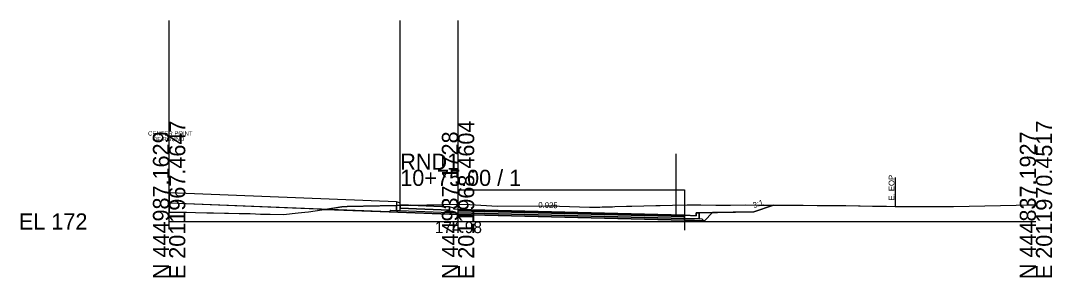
# Model space of a CAD drawing. Extents: x -26 to 153, y -10 to 6017.
# Drawn here: x -25.7 to 152.8, y 1490.3 to 1534.8 of the extents above; entities that cross this region are included whole.
import ezdxf

# ---------------------------------------------------------------- set-up
doc = ezdxf.new("R2010")
doc.units = 0
for name, color, linetype in [('Exist Cross Section Cell', 7, 'Continuous'), ('Exist XS Ground Line', 7, 'Continuous'), ('Prop CMT Conc Surface', 7, 'Continuous'), ('Prop CMT Concrete Structures', 7, 'Continuous'), ('Prop CMT Pvmt Course 1', 7, 'Continuous'), ('Prop CMT Pvmt Course 1 CG', 7, 'Continuous'), ('Prop CMT Pvmt Course 2', 7, 'Continuous'), ('Prop CMT Pvmt Course 3', 7, 'Continuous'), ('Prop CMT Pvmt Surface', 7, 'Continuous'), ('Prop CMT Shear Line', 7, 'Continuous'), ('Prop CMT Shear Line Text', 7, 'Continuous'), ('Prop CMT Slope Grass', 7, 'Continuous'), ('Prop CMT Subgrade Earthwork', 7, 'Continuous'), ('Prop XS Earthwork Shape', 7, 'Continuous'), ('Prop XS Label Text', 7, 'Continuous'), ('Prop XS SE Text', 7, 'Continuous'), ('Prop XS Side Slope Text', 7, 'Continuous'), ('Scratch_Level_1', 7, 'Continuous')]:
    doc.layers.add(name, color=color, linetype=linetype)

msp = doc.modelspace()

# ---------------------------------------------------------------- linework, layer by layer
at = {"layer": 'Exist Cross Section Cell'}
for p, q in [((50, 1500), (50, 1508.96)), ((0, 1500), (50, 1500)), ((50, 1500), (150, 1500))]:
    msp.add_line(p, q, dxfattribs=at)
at = {"layer": 'Exist XS Ground Line'}
msp.add_lwpolyline([(0, 1501.62), (1.6, 1501.62), (2.07, 1501.61), (2.68, 1501.61), (3, 1501.6), (4.59, 1501.54), (6.52, 1501.52), (7.09, 1501.51), (7.68, 1501.5), (9.59, 1501.43), (10.25, 1501.42), (12.1, 1501.38), (13.02, 1501.37), (14.04, 1501.36), (14.93, 1501.32), (15.79, 1501.29), (17.49, 1501.26), (19.81, 1501.21), (22.34, 1501.48), (23.51, 1501.6), (24.1, 1501.69), (26.41, 1501.99), (29.91, 1502.55), (30.8, 1502.57), (50.29, 1502.99), (52.03, 1502.93), (56.85, 1502.65), (65.22, 1502.7), (66.92, 1502.69), (67.55, 1502.67), (72.72, 1502.47), (73.83, 1502.48), (74.14, 1502.47), (74.54, 1502.5), (74.96, 1502.51), (76.73, 1502.55), (77.14, 1502.57), (79.15, 1502.64), (79.62, 1502.65), (80.08, 1502.66), (82.13, 1502.72), (84.25, 1502.75), (84.63, 1502.76), (84.99, 1502.77), (87.13, 1502.82), (89.64, 1502.87), (91.02, 1502.86), (91.56, 1502.87), (92, 1502.87), (94.63, 1502.85), (97.14, 1502.85), (99.69, 1502.86), (102.11, 1502.84), (103.21, 1502.83), (104.68, 1502.81), (107.1, 1502.82), (108.3, 1502.83), (108.73, 1502.83), (109.73, 1502.81), (112.12, 1502.79), (114.62, 1502.77), (117.12, 1502.74), (119.29, 1502.71), (119.61, 1502.7), (121.74, 1502.67), (122.11, 1502.66), (122.95, 1502.65), (124.12, 1502.63), (125.61, 1502.6), (129.55, 1502.61), (135.76, 1502.62), (146.58, 1502.85), (148.46, 1502.91), (150, 1502.9)], dxfattribs=at)
at = {"layer": 'Prop CMT Conc Surface'}
for points in [[(40, 1503.06), (39.96, 1503.17), (39.85, 1503.21), (39.34, 1503.4)], [(40, 1502.9), (40, 1503.06)], [(50, 1502.1), (49.25, 1502.12), (49.25, 1502.29), (48.5, 1502.54)], [(91.2, 1500.99), (91.2, 1501.49), (91.7, 1501.49)], [(89.21, 1501.12), (91.2, 1500.99)]]:
    msp.add_lwpolyline(points, dxfattribs=at)
at = {"layer": 'Prop CMT Concrete Structures'}
for points in [[(40, 1503.06), (39.96, 1503.17), (39.85, 1503.21), (39.34, 1503.4)], [(39.34, 1503.4), (39.34, 1501.9)], [(39.34, 1501.9), (40, 1501.9)], [(40, 1502.9), (40, 1503.06)], [(40, 1501.9), (40, 1502.9)], [(40, 1502.9), (40, 1502.31)], [(48.5, 1502.54), (40, 1502.88)], [(40, 1502.29), (48.5, 1501.95)], [(50, 1502.1), (49.25, 1502.12), (49.25, 1502.29), (48.5, 1502.54)], [(48.5, 1502.54), (48.5, 1501.55)], [(48.5, 1501.95), (48.5, 1502.54)], [(48.5, 1501.55), (50, 1501.52)], [(50, 1501.52), (50, 1502.1)], [(89.21, 1501.12), (91.2, 1500.99), (91.2, 1501.49), (91.7, 1501.49)], [(91.7, 1501.49), (91.7, 1500.47), (89.21, 1500.53)], [(89.21, 1500.53), (89.21, 1501.12)]]:
    msp.add_lwpolyline(points, dxfattribs=at)
at = {"layer": 'Prop CMT Pvmt Course 1'}
for points in [[(50, 1502.1), (89.21, 1501.12)], [(50, 1501.85), (50, 1502.1)], [(89.21, 1500.87), (50, 1501.85)], [(89.21, 1501.12), (89.21, 1500.87)]]:
    msp.add_lwpolyline(points, dxfattribs=at)
msp.add_lwpolyline([(50, 1501.85), (50, 1501.97), (50, 1501.97), (50, 1501.85)], close=True, dxfattribs=at)
at = {"layer": 'Prop CMT Pvmt Course 1 CG'}
for points in [[(50, 1501.18), (50, 1501.52)], [(89.21, 1500.53), (92.19, 1500.46), (92.53, 1500.12)], [(89.21, 1500.2), (89.21, 1500.53)], [(92.62, 1500.11), (89.21, 1500.2)]]:
    msp.add_lwpolyline(points, dxfattribs=at)
at = {"layer": 'Prop CMT Pvmt Course 2'}
for points in [[(50, 1501.52), (50, 1501.85)], [(50, 1501.85), (89.21, 1500.87)], [(89.21, 1500.53), (50, 1501.52)], [(89.21, 1500.87), (89.21, 1500.53)]]:
    msp.add_lwpolyline(points, dxfattribs=at)
at = {"layer": 'Prop CMT Pvmt Course 3'}
for points in [[(40, 1501.9), (48.5, 1501.55)], [(50, 1501.52), (89.21, 1500.53)], [(50, 1501.18), (50, 1501.52)], [(89.21, 1500.2), (50, 1501.18)], [(89.21, 1500.53), (89.21, 1500.2)]]:
    msp.add_lwpolyline(points, dxfattribs=at)
at = {"layer": 'Prop CMT Pvmt Surface'}
msp.add_lwpolyline([(50, 1502.1), (89.21, 1501.12)], dxfattribs=at)
at = {"layer": 'Prop CMT Shear Line'}
msp.add_line((0, 1498.64), (0, 1513.64), dxfattribs=at)
at = {"layer": 'Prop CMT Slope Grass'}
for p, q in [((39.34, 1503.38), (0, 1504.95)), ((38.06, 1501.66), (0, 1503.18))]:
    msp.add_line(p, q, dxfattribs=at)
msp.add_lwpolyline([(91.7, 1501.49), (101.16, 1501.68), (104.58, 1502.82)], dxfattribs=at)
at = {"layer": 'Prop CMT Subgrade Earthwork'}
for p, q in [((0, 1504.95), (0, 1501.62)), ((38.34, 1501.94), (38.06, 1501.66))]:
    msp.add_line(p, q, dxfattribs=at)
for points in [[(38.06, 1501.66), (50, 1501.18)], [(38.34, 1501.94), (39.34, 1501.9)], [(89.21, 1500.2), (92.62, 1500.11), (94.03, 1501.53)], [(50, 1501.18), (89.21, 1500.2)]]:
    msp.add_lwpolyline(points, dxfattribs=at)
at = {"layer": 'Prop XS Earthwork Shape'}
for points in [[(27.09, 1502.1), (0, 1503.18), (0, 1501.62), (1.6, 1501.62), (2.07, 1501.61), (2.68, 1501.61), (3, 1501.6), (4.59, 1501.54), (6.52, 1501.52), (7.09, 1501.51), (7.68, 1501.5), (9.59, 1501.43), (10.25, 1501.42), (12.1, 1501.38), (13.02, 1501.37), (14.04, 1501.36), (14.93, 1501.32), (15.79, 1501.29), (17.49, 1501.26), (19.81, 1501.21), (22.34, 1501.48), (23.51, 1501.6), (24.1, 1501.69), (26.41, 1501.99)], [(38.34, 1501.94), (39.34, 1501.9), (39.34, 1502.75), (30.8, 1502.57), (29.91, 1502.55), (27.09, 1502.1), (38.06, 1501.66)], [(48.5, 1501.55), (50, 1501.52), (50, 1502.1), (89.21, 1501.12), (89.21, 1500.53), (91.7, 1500.47), (91.7, 1501.49), (94.03, 1501.53), (92.62, 1500.11), (89.21, 1500.2), (50, 1501.18), (38.06, 1501.66), (38.34, 1501.94), (39.34, 1501.9), (40, 1501.9), (40, 1502.29), (48.5, 1501.95)], [(39.34, 1502.75), (39.34, 1501.9), (40, 1501.9), (40, 1502.29), (40, 1502.31), (40, 1502.77)], [(40, 1502.77), (41.77, 1502.81), (48.5, 1502.54), (48.5, 1501.95), (40, 1502.29), (40, 1502.31)], [(103.21, 1502.83), (104.58, 1502.82), (101.16, 1501.68), (94.03, 1501.53), (91.7, 1501.49), (91.2, 1501.49), (91.2, 1500.99), (89.21, 1501.12), (50, 1502.1), (49.25, 1502.12), (49.25, 1502.29), (48.5, 1502.54), (41.77, 1502.81), (50.29, 1502.99), (52.03, 1502.93), (56.85, 1502.65), (65.22, 1502.7), (66.92, 1502.69), (67.55, 1502.67), (72.72, 1502.47), (73.83, 1502.48), (74.14, 1502.47), (74.54, 1502.5), (74.96, 1502.51), (76.73, 1502.55), (77.14, 1502.57), (79.15, 1502.64), (79.62, 1502.65), (80.08, 1502.66), (82.13, 1502.72), (84.25, 1502.75), (84.63, 1502.76), (84.99, 1502.77), (87.13, 1502.82), (89.64, 1502.87), (91.02, 1502.86), (91.56, 1502.87), (92, 1502.87), (94.63, 1502.85), (97.14, 1502.85), (99.69, 1502.86), (102.11, 1502.84)], [(48.5, 1501.55), (50, 1501.52), (50, 1502.1), (49.25, 1502.12), (49.25, 1502.29), (48.5, 1502.54), (48.5, 1501.95)], [(89.21, 1500.53), (89.21, 1501.12), (91.2, 1500.99), (91.2, 1501.49), (91.7, 1501.49), (91.7, 1500.47)]]:
    msp.add_lwpolyline(points, close=True, dxfattribs=at)
at = {"layer": 'Prop XS Label Text'}
msp.add_line((125.61, 1507.6), (125.61, 1502.6), dxfattribs=at)
at = {"layer": 'Scratch_Level_1'}
for p, q in [((0, 1502.1), (0, 1534.82)), ((40, 1502.1), (40, 1534.82)), ((50, 1502.1), (50, 1534.82)), ((87.74, 1501.23), (87.74, 1511.75))]:
    msp.add_line(p, q, dxfattribs=at)
msp.add_lwpolyline([(50, 1505.49), (89.21, 1505.49), (89.21, 1498.52)], dxfattribs=at)

# ---------------------------------------------------------------- texts
at = {"layer": 'Exist Cross Section Cell'}
for s, p in [('E 2011967.4647', (2.8, 1490)), ('E 2011968.4604', (52.8, 1490)), ('E 2011970.4517', (152.8, 1490)), ('N 444987.1629', (0, 1490)), ('N 444937.1728', (50, 1490)), ('N 444837.1927', (150, 1490))]:
    msp.add_text(s, height=2.8, rotation=90, dxfattribs=at).set_placement(p)
for s, p in [('RND1', (40, 1508.96)), ('10+75.00 / 1', (40, 1506.16)), ('EL 172', (-26, 1498.6))]:
    msp.add_text(s, height=2.8, dxfattribs=at).set_placement(p)
at = {"layer": 'Exist XS Ground Line'}
msp.add_text('174.98', height=2, dxfattribs=at).set_placement((45.96, 1497.98))
at = {"layer": 'Prop CMT Shear Line Text'}
for s, p in [('CENTER POINT', (-3.64, 1514.89)), ('OF ROUND', (-2.88, 1513.92))]:
    msp.add_text(s, height=0.75, dxfattribs=at).set_placement(p)
at = {"layer": 'Prop XS Label Text'}
msp.add_text('E. EOP', height=1, rotation=90, dxfattribs=at).set_placement((125.51, 1503.62))
at = {"layer": 'Prop XS SE Text'}
msp.add_text('0.025', height=1, rotation=358.5613, dxfattribs=at).set_placement((63.87, 1502.38))
at = {"layer": 'Prop XS Side Slope Text'}
msp.add_text('3:1', height=1, rotation=18.4349, dxfattribs=at).set_placement((101.2, 1502.3))

doc.saveas('drawing.dxf')
